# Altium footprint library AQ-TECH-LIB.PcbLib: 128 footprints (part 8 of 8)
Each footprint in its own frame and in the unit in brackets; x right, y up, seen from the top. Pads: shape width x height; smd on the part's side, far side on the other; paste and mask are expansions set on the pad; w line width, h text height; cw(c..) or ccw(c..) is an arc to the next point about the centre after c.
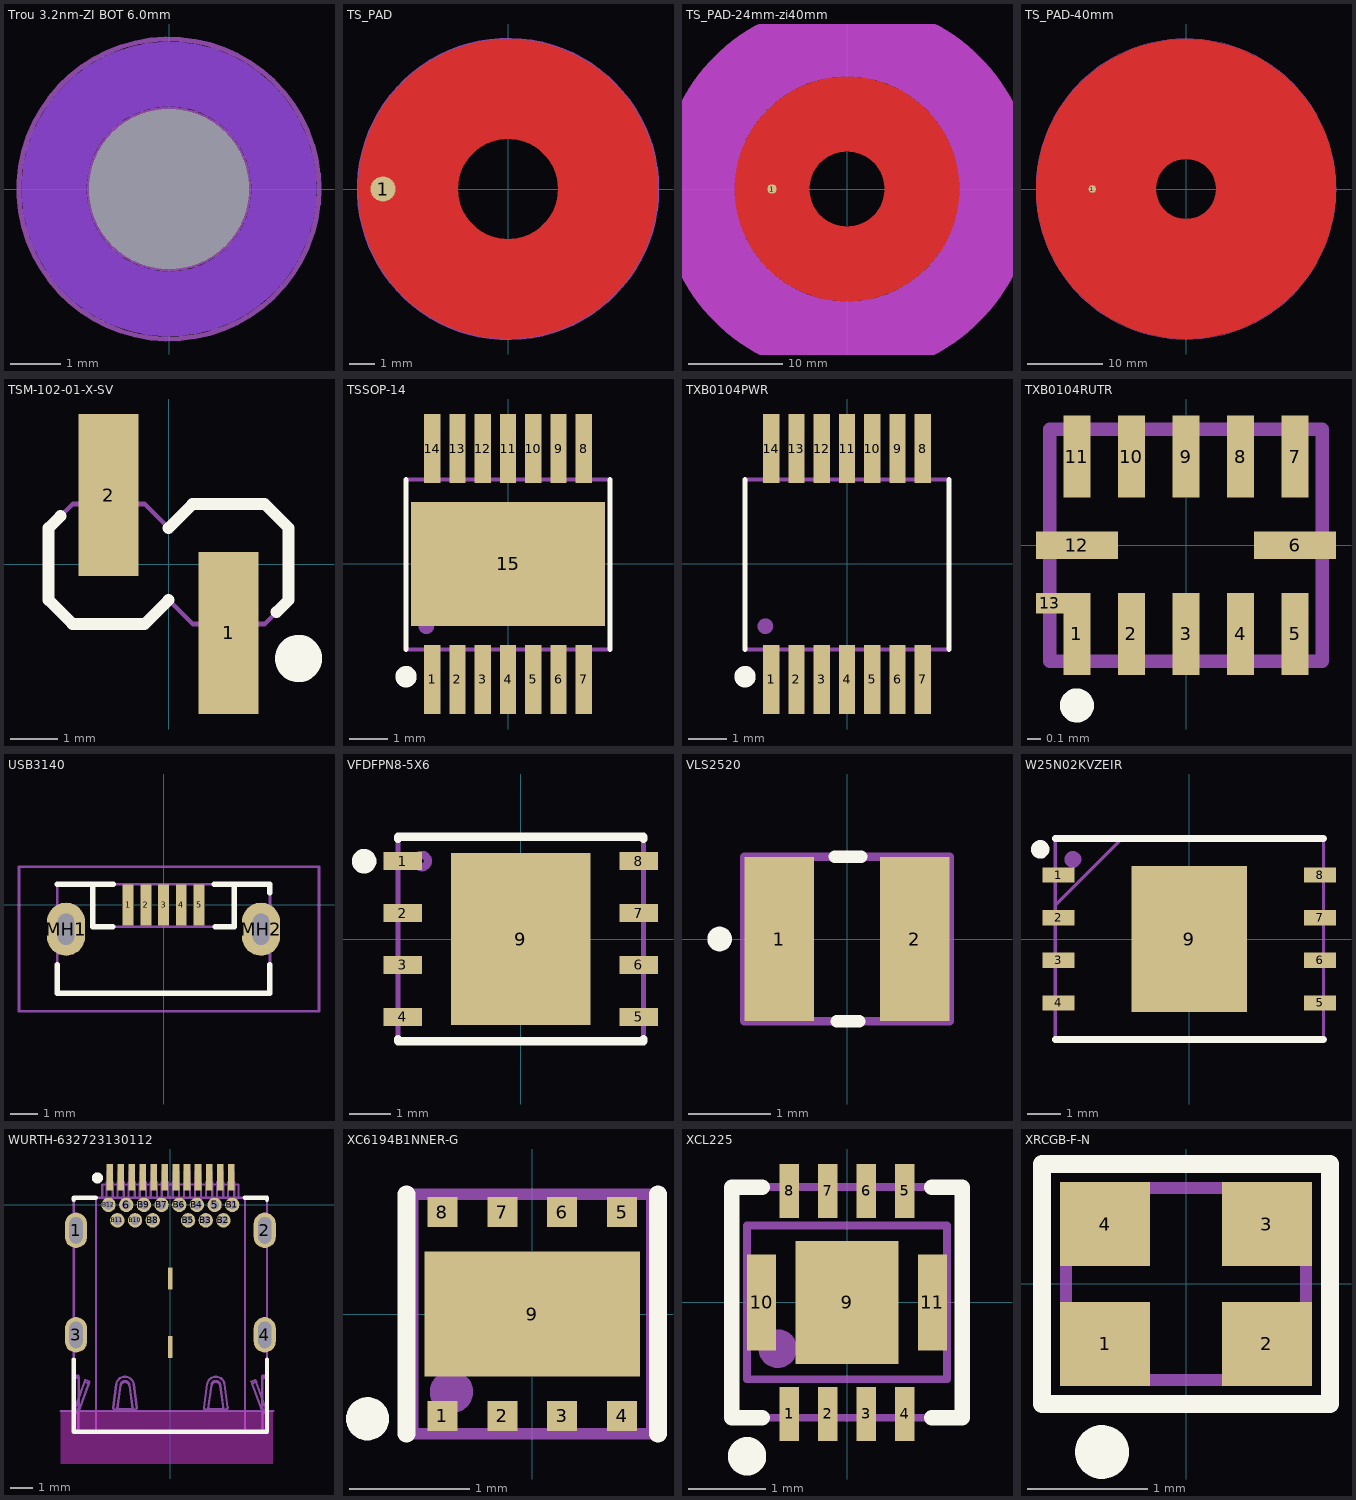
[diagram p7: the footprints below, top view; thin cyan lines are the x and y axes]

## Trou 3.2nm-ZI BOT 6.0mm [mm]
pads (1):
  round 0 hole 3.2 paste+0 mask+1.7: 1(0,0)
Bottom Layer keep-out:
  circle w1.3: c0,0 r2.3
Mechanical 3:
  circle w0.1: c0,0 r1.6
Mechanical 13:
  circle w0.1: c0,0 r3

## TS_PAD [mm]
pads (1):
  round 1 smd paste-2 mask+0.1: 1(-5,0)
Top Layer:
  lines w4: -4,0 ccw(c0,0) 4,0 ccw(c0,0) -4,0
Top Solder:
  circle w4.4: c0,0 r4
Mechanical 3:
  circle w0.1: c0,0 r6
  text "'.Designator'" at 1.55,4.425 h1

## TS_PAD-24mm-zi40mm [mm]
pads (1):
  round 1 smd paste-2 mask+0.1: 1(-8,0)
Top Layer:
  lines w8: -8,0 cw(c0,0) 8,0 cw(c0,0) -8,0
Top Layer keep-out:
  circle w8: c0,0 r16
Top Solder:
  circle w8.4: c0,0 r8
Mechanical 3:
  circle w0.1: c0,0 r12
  circle w8: c0,0 r16
  text "'.Designator'" at 0,0 h1

## TS_PAD-40mm [mm]
pads (1):
  round 1 smd paste-2 mask+0.1: 1(-12.5,0)
Top Layer:
  lines w16: -12,0 ccw(c0,0) 12,0 ccw(c0,0) -12,0
Top Solder:
  circle w16.4: c0,0 r12
Mechanical 3:
  circle w0.1: c0,0 r20
  text "'.Designator'" at 0,0 h1

## TSM-102-01-X-SV [mm]
height 9.65
pads (2):
  rect 1.27x3.43 smd: 1(1.27,-1.46) 2(-1.27,1.46)
Top Overlay:
  circle w0.5: c2.75,-2 r0.25
  lines w0.25: -2.286,1.016 -2.54,0.762 -2.54,-0.762 -2.032,-1.27 -0.508,-1.27 0,-0.762 ; 0,0.762 0.508,1.27 2.032,1.27 2.54,0.762 2.54,-0.762 2.286,-1.016
Mechanical 3:
  lines w0.1: -2.54,-0.762 -2.032,-1.27 -0.508,-1.27 0,-0.762 0.508,-1.27 2.032,-1.27 2.54,-0.762 2.54,0.762 2.032,1.27 0.508,1.27 0,0.762 -0.508,1.27 -2.032,1.27 -2.54,0.762 -2.54,-0.762 ; -1.651,1.27 -1.651,2.794 -0.889,2.794 -0.889,1.27 -1.651,1.27 ; 0.889,-2.921 0.889,-1.397 1.651,-1.397 1.651,-2.921 0.889,-2.921
  text ".Designator" at 0.714,0.439 h0.84
  text "1" at 2.286,-2.794 h0.84
  text "2" at -2.794,1.27 h0.84
3D body "TSM-102-01-F-SV-P-TR.stp": height 10.9, standoff -0.02, extent -5.08,-2.641 5.08,2.642

## TSSOP-14 [mm]
height 1.2
pads (15):
  rect 0.42x1.78 smd paste+0 mask+0.05: 1(-1.95,-2.97) 2(-1.3,-2.97) 3(-0.65,-2.97) 4(0,-2.97) 5(0.65,-2.97) 6(1.3,-2.97) 7(1.95,-2.97) 8(1.95,2.97) 9(1.3,2.97) 10(0.65,2.97) 11(0,2.97) 12(-0.65,2.97) 13(-1.3,2.97) 14(-1.95,2.97)
  rect 5x3.2 smd paste+0 mask+0.05: 15(0,0)
Top Overlay:
  circle w0.4: c-2.625,-2.9 r0.075
  lines w0.125: -2.625,-2.2 -2.625,2.175 ; 2.625,-2.2 2.625,2.175
Mechanical 3:
  circle w0.2: c-2.1,-1.6 r0.1
  lines w0.1: -2.625,-2.2 -2.625,2.175 2.625,2.175 2.625,-2.2 -2.625,-2.2
  text "'.Designator'" at 0,0 h1
3D body "TSSOP14(refusion).stp": height 1.1, standoff 0, extent -2.5,-3.2 2.5,3.2

## TXB0104PWR [mm]
height 1.2
pads (14):
  rect 0.42x1.78 smd paste+0 mask+0.05: 1(-1.95,-2.97) 2(-1.3,-2.97) 3(-0.65,-2.97) 4(0,-2.97) 5(0.65,-2.97) 6(1.3,-2.97) 7(1.95,-2.97) 8(1.95,2.97) 9(1.3,2.97) 10(0.65,2.97) 11(0,2.97) 12(-0.65,2.97) 13(-1.3,2.97) 14(-1.95,2.97)
Top Overlay:
  circle w0.4: c-2.625,-2.9 r0.075
  lines w0.125: -2.625,-2.2 -2.625,2.175 ; 2.625,-2.2 2.625,2.175
Mechanical 3:
  circle w0.2: c-2.1,-1.6 r0.1
  lines w0.1: -2.625,-2.2 -2.625,2.175 2.625,2.175 2.625,-2.2 -2.625,-2.2
  text "'.Designator'" at 0,0 h1
3D body "TSSOP14(refusion).stp": height 1.1, standoff 0, extent -2.5,-3.2 2.5,3.2

## TXB0104RUTR [mm]
pads (13):
  rect 0.2x0.6 smd mask+0.05: 1(-0.8,-0.65) 2(-0.4,-0.65) 3(0,-0.65) 4(0.4,-0.65) 5(0.8,-0.65) 7(0.8,0.65) 8(0.4,0.65) 9(0,0.65) 10(-0.4,0.65) 11(-0.8,0.65)
  rect 0.6x0.2 smd mask+0.05: 6(0.8,0) 12(-0.8,0)
  rect 0.2x0.15 smd mask+0.05: 13(-1,-0.425)
Top Overlay:
  circle w0.15: c-0.8,-1.175 r0.05
Mechanical 3:
  lines w0.1: -1,-0.85 1,-0.85 1,0.85 -1,0.85 -1,-0.85
  text "'.Designator'" at 0,0 h1
3D body "TXB0104RUTR.stp": height 0.55, standoff 0, extent -1,-0.85 1,0.85

## USB3140 [mm] "MICRO USB TYPE B VERTICAL"
height 6.5
pads (7):
  rect 0.4x1.5 smd mask+0.05: 1(-1.3,0) 2(-0.65,0) 3(0,0) 4(0.65,0) 5(1.3,0)
  oval 1.4x1.95 hole 0.6 slot 1.15 at 90 deg mask+0.1: MH1(-3.575,-0.89) MH2(3.575,-0.89)
Top Overlay:
  lines w0.2: -3.9,-2.201 -3.9,-3.24 3.9,-3.24 3.9,-2.201 ; -3.9,0.76 -1.841,0.76 ; -2.6,0.75 -2.6,-0.8 -1.857,-0.8 ; 1.86,0.76 3.9,0.76 3.9,0.44 ; 1.899,-0.8 2.6,-0.8 2.6,0.76
Mechanical 3:
  lines w0.1: -2.6,0.75 -2.6,-0.8 2.6,-0.8 2.6,0.237 2.6,0.76 ; -5.3,-3.9 -5.3,1.4 5.7,1.4 5.7,-3.9 -5.3,-3.9 ; -3.9,-3.24 3.9,-3.24 3.9,0.76 -3.9,0.76 -3.9,-1.627 -3.9,-3.24
  text ".Designator" at 0.25,-1.4 h0.84
3D body: height 7.5, standoff 4.5, extent 5,-3.9 5.7,1.4
3D body: height 7.5, standoff 6.5, extent -5.3,-3.9 5.7,1.4
3D body: height 6.5, standoff 0, extent -3.9,-3.24 3.9,0.76
3D body: height 6.51, standoff 0, extent -2.6,-0.8 2.6,0.238

## VFDFPN8-5X6 [mm]
height 1
pads (9):
  rect 0.94x0.44 smd mask+0.05: 1(-2.885,1.905) 2(-2.885,0.635) 3(-2.885,-0.635) 4(-2.885,-1.905) 5(2.885,-1.905) 6(2.885,-0.635) 7(2.885,0.635) 8(2.885,1.905)
  rect 3.4x4.2 smd paste-3 mask+0.05: 9(0,0)
Top Overlay:
  circle w0.3: c-3.825,1.9 r0.15
  lines w0.2: -3,-2.445 -3,-2.5 3,-2.5 3,-2.445 ; -3,2.445 -3,2.5 3,2.5 3,2.445
Top Paste:
  region: -0.23,0.23 -1.24,0.23 -1.24,1.64 -0.23,1.64
  region: -0.23,-1.64 -1.24,-1.64 -1.24,-0.23 -0.23,-0.23
  region: 1.24,0.23 0.23,0.23 0.23,1.64 1.24,1.64
  region: 1.24,-1.64 0.23,-1.64 0.23,-0.23 1.24,-0.23
Mechanical 3:
  circle w0.2: c-2.415,1.905 r0.15
  lines w0.127: -3,-2.5 -3,2.5 3,2.5 3,-2.5 -3,-2.5
  text ".Designator" at -1.95,-0.124 h0.84
3D body: height 1, standoff 0, extent -3,-2.5 3,2.5
3D body: height 1.01, standoff 0, extent -2.665,1.655 -2.165,2.155

## VLS2520 [mm]
height 1.2
pads (2):
  rect 0.85x2 smd: 1(-0.825,0) 2(0.825,0)
Top Overlay:
  circle w0.2: c-1.55,0 r0.05
  lines w0.15: -0.15,1 0.175,1 ; -0.125,-1 0.15,-1
Mechanical 3:
  lines w0.1: -1.25,-1 -1.25,1 1.25,1 1.25,-1 -1.25,-1
  text ".Designator" at -0.45,-0.075 h0.84
3D body "VLS252010CX-1R0M-1.stp": height 1, standoff 0, extent -1.25,-1 1.25,1

## W25N02KVZEIR [mm] "WSON-8  8X6MM"
height 0.8
pads (9):
  rect 0.95x0.45 smd: 1(-3.9,1.905) 2(-3.9,0.635) 3(-3.9,-0.635) 4(-3.9,-1.905) 5(3.9,-1.905) 6(3.9,-0.635) 7(3.9,0.635) 8(3.9,1.905)
  rect 3.45x4.35 smd: 9(0,0)
Top Overlay:
  circle w0.3: c-4.45,2.675 r0.125
  lines w0.2: -4,-3 4,-3 ; -4,3 4,3
Mechanical 3:
  circle w0.3: c-3.475,2.375 r0.1
  lines w0.1: -4,1 -2,3 ; -4,-3 4,-3 4,3 -4,3 -4,-3
3D body "W25N02KVZEIR.stp": height 0.8, standoff 0, extent -4.05,-3 4.05,3

## WURTH-632723130112 [mm] "WR-COM USB 3.1 HORIZONTAL SMT"
height 2
pads (32):
  rect 0.2x1 smd paste-2 mask+0.05: 0(0,-6.43) 0(0,-3.33)
  oval 1x1.6 hole 0.6 slot 1.2 at 90 deg: 1(-4.27,-1.15) 2(4.27,-1.15) 3(-4.27,-5.88) 4(4.27,-5.88)
  round 0.65 hole 0.4 paste-2 mask+0.1: 5(2,0) 6(-2,0) B1(2.8,0) B2(2.4,-0.7) B3(1.6,-0.7) B4(1.2,0) B5(0.8,-0.7) B6(0.4,0) B7(-0.4,0) B8(-0.8,-0.7) B9(-1.2,0) B10(-1.6,-0.7) B11(-2.4,-0.7) B12(-2.8,0)
  rect 0.3x1.2 smd mask+0.05: A1(-2.75,1.25) A2(-2.25,1.25) A3(-1.75,1.25) A4(-1.25,1.25) A5(-0.75,1.25) A6(-0.25,1.25) A7(0.25,1.25) A8(0.75,1.25) A9(1.25,1.25) A10(1.75,1.25) A11(2.25,1.25) A12(2.75,1.25)
Top Layer keep-out:
  rectangle: -4.975,-11.725 4.65,-9.325
Top Overlay:
  circle w0.3: c-3.305,1.22 r0.1
  lines w0.2: -4.37,-6.995 -4.37,-10.275 4.37,-10.275 4.37,-6.995 ; -4.37,0.225 -4.37,0.325 -3.37,0.325 ; 3.37,0.325 4.37,0.325 4.37,0.225
Mechanical 3:
  drawing of 920 lines, arcs and shapes, not listed
  text ".Designator" at 0.025,-2.025 h0.84
Mechanical 32:
  lines w0.1: -4.975,-9.325 4.65,-9.325
3D body "632723100011_Download_STP_632723100011_rev1.stp": height 3.03, standoff -1.83, extent -4.37,-10.275 4.37,1.519

## XC6194B1NNER-G [mm]
height 0.3
pads (9):
  rect 0.25x0.25 smd mask+0.05: 1(-0.75,-0.85) 2(-0.25,-0.85) 3(0.25,-0.85) 4(0.75,-0.85) 5(0.75,0.85) 6(0.25,0.85) 7(-0.25,0.85) 8(-0.75,0.85)
  rect 1.8x1.04 smd mask+0.05: 9(0,0)
Top Overlay:
  circle w0.2: c-1.375,-0.875 r0.08
  lines w0.15: -1.05,-1 -1.05,1 ; 1.05,-1 1.05,1
Mechanical 3:
  circle w0.2: c-0.675,-0.65 r0.08
  lines w0.1: -1,-1 -1,1 1,1 1,-1 -1,-1
3D body "XC6194B1NNER-G.stp": height 0.33, standoff 0, extent -1,-1 1,1

## XCL225 [mm]
height 1.7
pads (11):
  rect 0.25x0.7 smd mask+0.05: 1(-0.75,-1.45) 2(-0.25,-1.45) 3(0.25,-1.45) 4(0.75,-1.45) 5(0.75,1.45) 6(0.25,1.45) 7(-0.25,1.45) 8(-0.75,1.45)
  rect 1.34x1.6 smd mask+0.05: 9(0,0)
  rect 0.38x1.25 smd mask+0.05: 10(-1.11,0) 11(1.11,0)
Top Overlay:
  circle w0.3: c-1.3,-2 r0.1
  lines w0.2: -1.1,-1.5 -1.5,-1.5 -1.5,1.5 -1.1,1.5 ; 1.1,-1.5 1.5,-1.5 1.5,1.5 1.1,1.5
Mechanical 3:
  circle w0.3: c-0.9,-0.6 r0.1
  lines w0.1: -1.5,-1.5 -1.5,1.5 1.5,1.5 1.5,-1.5 -1.5,-1.5 ; -1.3,-1 1.3,-1 1.3,1 -1.3,1 -1.3,-1
  text ".Designator" at 0.55,-0.5 h0.84
3D body: height 0.5, standoff 0, extent -1.5,-1.5 1.5,1.5
3D body: height 1.21, standoff 0, extent -1.149,-0.85 -0.651,-0.35
3D body: height 1.2, standoff 0, extent -1.3,-1 1.3,1

## XRCGB-F-N [mm]
height 0.7
pads (4):
  rect 0.75x0.7 smd: 1(-0.675,-0.5) 2(0.675,-0.5) 3(0.675,0.5) 4(-0.675,0.5)
Top Overlay:
  circle w0.25: c-0.7,-1.4 r0.1
  lines w0.15: -1.2,-1 1.2,-1 1.2,1 -1.2,1 -1.2,-1
Mechanical 3:
  circle w0.2: c-0.675,-0.5 r0.05
  lines w0.1: -1,-0.8 -1,0.8 1,0.8 1,-0.8 -1,-0.8
  text ".Designator" at -1.95,-2 h0.84
3D body: height 0.7, standoff 0, extent -1,-0.8 1,0.8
